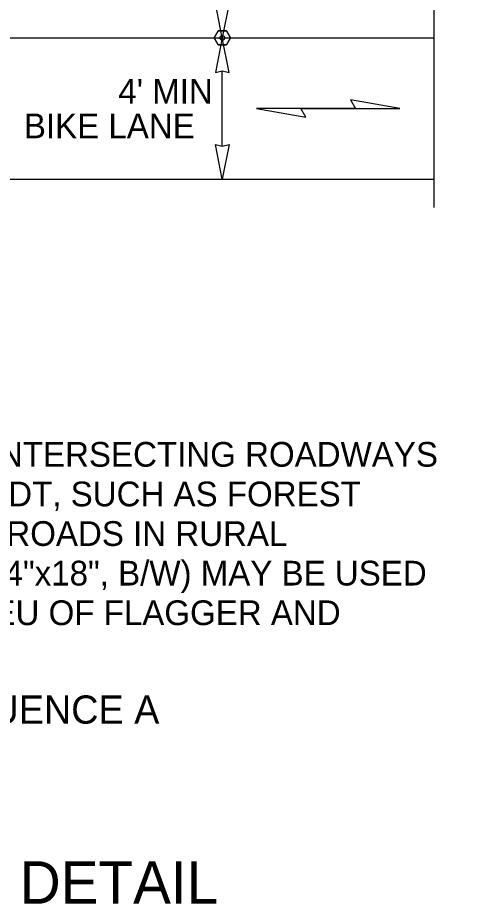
# Model space of a CAD drawing. Extents: x 99999.1 to 100095.7, y 99995 to 100010.7.
# Drawn here: x 100063.846 to 100065.105, y 100001.874 to 100004.382 of the extents above; entities that cross this region are included whole.
import ezdxf

# ---------------------------------------------------------------- set-up
doc = ezdxf.new("R2010")
doc.units = 0
for name, color, linetype in [('RD_ED_ShoulderPavedEdge', 7, 'Continuous'), ('RD_MK_LineEdgeWhite', 7, 'Continuous'), ('SH_DE_DetailHeading2Text', 7, 'Continuous'), ('TR_WZ_TubularMarker', 7, 'Continuous'), ('TR_WZ_WorkZoneDetails', 7, 'Continuous'), ('TR_WZ_WorkZoneTextCurrent', 7, 'Continuous')]:
    doc.layers.add(name, color=color, linetype=linetype)

msp = doc.modelspace()

# ---------------------------------------------------------------- linework, layer by layer
at = {"layer": 'RD_ED_ShoulderPavedEdge'}
msp.add_line((100063.085, 100003.9249), (100065.025, 100003.9249), dxfattribs=at)
at = {"layer": 'RD_MK_LineEdgeWhite'}
msp.add_line((100063.085, 100004.3249), (100065.025, 100004.3249), dxfattribs=at)
at = {"layer": 'TR_WZ_TubularMarker'}
msp.add_lwpolyline([(100064.4026, 100004.3249), (100064.4141, 100004.3449), (100064.4372, 100004.3449), (100064.4488, 100004.3249), (100064.4372, 100004.3049), (100064.4141, 100004.3049)], close=True, dxfattribs=at)
msp.add_lwpolyline([(100064.4141, 100004.3049), (100064.4372, 100004.3049), (100064.4488, 100004.3249), (100064.4372, 100004.3449), (100064.4141, 100004.3449), (100064.4026, 100004.3249), (100064.4141, 100004.3049)], dxfattribs=at)
msp.add_circle((100064.4257, 100004.3249), 0.00667, dxfattribs=at)
at = {"layer": 'TR_WZ_WorkZoneDetails'}
for p, q in [((100064.4256, 100004.0187), (100064.4256, 100004.2312)), ((100064.8025, 100004.1249), (100064.6482, 100004.1249)), ((100064.6482, 100004.1249), (100064.8025, 100004.1249))]:
    msp.add_line(p, q, dxfattribs=at)
msp.add_lwpolyline([(100065.025, 100003.8449), (100065.025, 100004.7275), (100064.945, 100004.7275), (100065.105, 100004.8824), (100065.025, 100004.8824), (100065.025, 100005.7649)], dxfattribs=at)
for points in [[(100064.4256, 100004.3249), (100064.4064, 100004.4232), (100064.4256, 100004.4187), (100064.4449, 100004.4232)], [(100064.4256, 100004.3249), (100064.4064, 100004.2266), (100064.4256, 100004.2312), (100064.4449, 100004.2266)], [(100064.9283, 100004.1249), (100064.7882, 100004.1496), (100064.8025, 100004.1249)], [(100064.5224, 100004.1249), (100064.6624, 100004.1002), (100064.6482, 100004.1249)], [(100064.4256, 100003.9249), (100064.4064, 100004.0232), (100064.4256, 100004.0187), (100064.4449, 100004.0232)]]:
    msp.add_lwpolyline(points, close=True, dxfattribs=at)

# ---------------------------------------------------------------- texts
at = {"layer": 'SH_DE_DetailHeading2Text'}
msp.add_text('UNSIGNALIZED INTERSECTING ROADWAY DETAIL', height=0.12, rotation=360, dxfattribs=at).set_placement((100060.5086, 100001.8759))
at = {"layer": 'TR_WZ_WorkZoneDetails'}
for s, p in [('ON LOW-VOLUME INTERSECTING ROADWAYS ', (100062.935, 100003.1118)), ('(LESS THAN 400 AADT, SUCH AS FOREST ', (100062.935, 100002.9998)), ('ROADS OR TRIBAL ROADS IN RURAL ', (100062.935, 100002.8878)), ('AREAS), G25-101 (24"x18", B/W) MAY BE USED ', (100062.935, 100002.7758)), ('AT STOP BAR IN LIEU OF FLAGGER AND ', (100062.935, 100002.6638))]:
    msp.add_text(s, height=0.07, dxfattribs=at).set_placement(p)
at = {"layer": 'TR_WZ_WorkZoneTextCurrent'}
for s, height, p in [("4' MIN", 0.07, (100064.1312, 100004.1389)), ('BIKE LANE', 0.07, (100063.8637, 100004.0409)), ('USE SIGN SEQUENCE A', 0.08, (100063.005, 100002.3849))]:
    msp.add_text(s, height=height, dxfattribs=at).set_placement(p)

doc.saveas('drawing.dxf')
